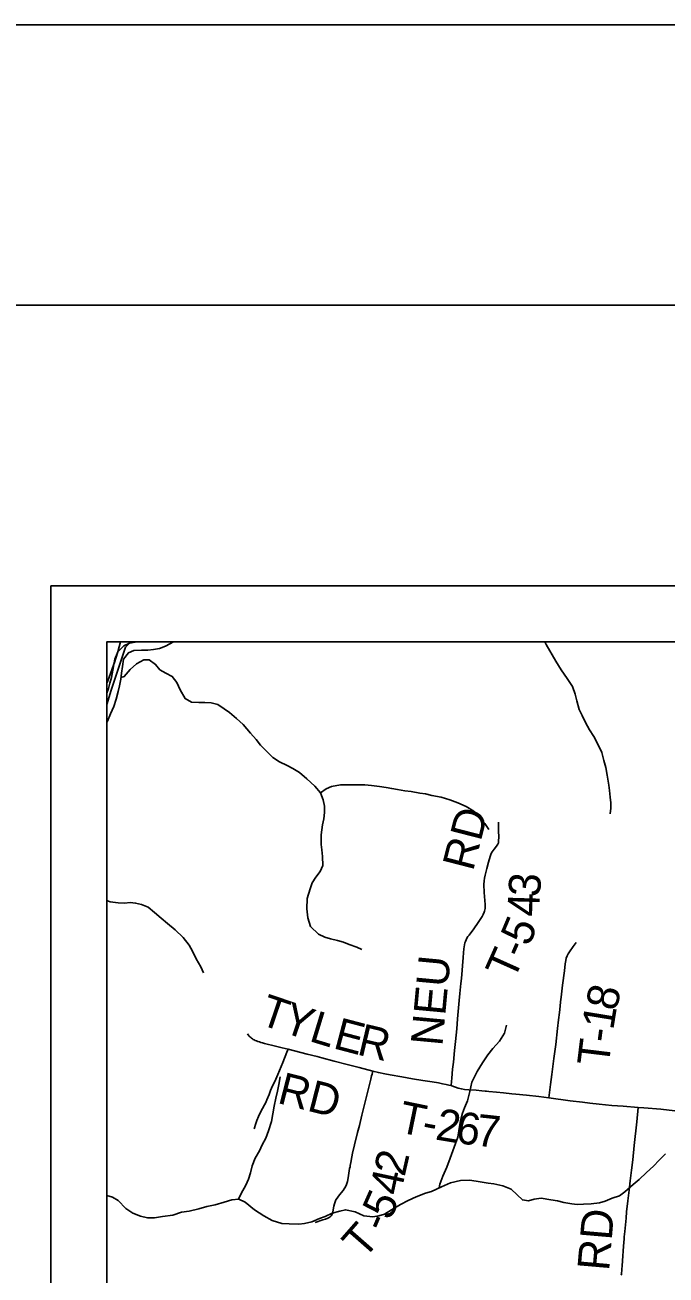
# Model space of a CAD drawing. Extents: x 0 to 34, y 0 to 22.
# Drawn here: x 2.168 to 3.312, y 19.77 to 22 of the extents above; entities that cross this region are included whole.
import ezdxf

# ---------------------------------------------------------------- set-up
doc = ezdxf.new("R2010")
doc.units = 0
for name, color, linetype in [('Default', 7, 'Continuous'), ('GM_X_County_Road', 7, 'Continuous'), ('GM_X_Minor_River', 7, 'Continuous'), ('GM_X_Township_Road', 7, 'Continuous'), ('GM_X_Township_Road_Text', 7, 'Continuous'), ('SH_Border', 7, 'Continuous'), ('SH_Cut_Line', 7, 'Continuous'), ('SH_Data', 7, 'Continuous')]:
    doc.layers.add(name, color=color, linetype=linetype)

msp = doc.modelspace()

# ---------------------------------------------------------------- linework, layer by layer
at = {"layer": 'Default'}
msp.add_lwpolyline([(8.6167, 20.8996), (2.3571, 20.8996), (2.3471, 20.8898), (2.3219, 20.8131), (2.3142, 20.7876), (2.3142, 19.0219)], dxfattribs=at)
msp.add_lwpolyline([(2.3571, 20.8996), (2.3142, 20.8996), (2.3142, 20.7876), (2.3219, 20.8131), (2.3471, 20.8898)], close=True, dxfattribs=at)
at = {"layer": 'GM_X_County_Road'}
msp.add_lwpolyline([(2.3142, 20.8255), (2.3158, 20.8301), (2.3282, 20.8645), (2.3302, 20.8704), (2.3335, 20.8817), (2.3383, 20.8996)], dxfattribs=at)
at = {"layer": 'GM_X_Minor_River'}
for points in [[(2.3142, 20.7553), (2.3152, 20.7582), (2.3207, 20.771), (2.3262, 20.7842), (2.3306, 20.797), (2.3342, 20.8106), (2.3363, 20.8208), (2.3387, 20.8329), (2.34, 20.8435), (2.3417, 20.8553), (2.3439, 20.8685), (2.3524, 20.8797), (2.3623, 20.8841), (2.3759, 20.8847), (2.3869, 20.8845), (2.3971, 20.8859), (2.4081, 20.8876), (2.4188, 20.8916), (2.4329, 20.8994), (2.4335, 20.8996)], [(2.3794, 20.8996), (2.3784, 20.8994), (2.3682, 20.8992), (2.3542, 20.8972), (2.3443, 20.8924), (2.3339, 20.8815), (2.328, 20.8687), (2.3267, 20.8589), (2.3246, 20.8491), (2.3221, 20.8358), (2.3193, 20.826), (2.3169, 20.8162), (2.3142, 20.8078)], [(3.096, 20.8996), (3.0979, 20.8948), (3.1155, 20.8649), (3.1251, 20.8496), (3.1358, 20.8339), (3.1451, 20.8201), (3.1498, 20.806), (3.1526, 20.7945), (3.1569, 20.7789), (3.1624, 20.7682), (3.1682, 20.7556), (3.1752, 20.7426), (3.1833, 20.7304), (3.1914, 20.7143), (3.1972, 20.7021), (3.2012, 20.6876), (3.2048, 20.6754), (3.2068, 20.6617), (3.2099, 20.6438), (3.2113, 20.6343), (3.2126, 20.6226), (3.2136, 20.6123), (3.2134, 20.6025), (3.2125, 20.5926)], [(2.3391, 20.836), (2.3452, 20.8378), (2.3557, 20.8501), (2.3672, 20.8605), (2.3798, 20.8672), (2.3896, 20.8674), (2.4009, 20.8593), (2.4086, 20.8493), (2.4191, 20.8434), (2.4308, 20.8376), (2.4389, 20.8268), (2.4448, 20.8138), (2.4536, 20.7982), (2.4648, 20.7919), (2.4781, 20.791), (2.4887, 20.7915), (2.5, 20.7906), (2.5121, 20.7878), (2.5233, 20.78), (2.533, 20.7734), (2.5454, 20.763), (2.5573, 20.7522), (2.5707, 20.7364), (2.5803, 20.7253), (2.5885, 20.7153), (2.5981, 20.7053), (2.6104, 20.693), (2.622, 20.6852), (2.6359, 20.6789), (2.6457, 20.6738), (2.6581, 20.6664), (2.6711, 20.6552), (2.6853, 20.6421), (2.6953, 20.6298), (2.7004, 20.6176), (2.7025, 20.6066), (2.7023, 20.5952), (2.701, 20.5835), (2.6989, 20.5729), (2.6963, 20.5551), (2.6968, 20.538), (2.6978, 20.5285), (2.6991, 20.5167), (2.6996, 20.5004), (2.6945, 20.4895), (2.6868, 20.4794), (2.6805, 20.4696), (2.677, 20.459), (2.6718, 20.4417), (2.6711, 20.4231), (2.6727, 20.4071), (2.6777, 20.3915), (2.6915, 20.378), (2.7032, 20.3725), (2.7133, 20.3697), (2.7258, 20.3669), (2.7363, 20.3637), (2.7465, 20.3597), (2.7604, 20.355), (2.7694, 20.3506)], [(2.6953, 20.6298), (2.7053, 20.6372), (2.7152, 20.6413), (2.7311, 20.6441), (2.7436, 20.6446), (2.7743, 20.6441), (2.7864, 20.6432), (2.8007, 20.6411), (2.8128, 20.6394), (2.8226, 20.6377), (2.8328, 20.636), (2.846, 20.6336), (2.8573, 20.6322), (2.8724, 20.6297), (2.8826, 20.6281), (2.8939, 20.6256), (2.9105, 20.6223), (2.926, 20.6179), (2.9407, 20.6124), (2.9553, 20.6057), (2.9688, 20.5971), (2.9781, 20.5868), (2.9885, 20.5752), (2.9959, 20.5649)], [(2.3142, 20.4378), (2.3197, 20.4357), (2.334, 20.4336), (2.3454, 20.4334), (2.3556, 20.4344), (2.3654, 20.4335), (2.376, 20.4311), (2.388, 20.426), (2.3992, 20.4167), (2.4108, 20.4063), (2.4224, 20.397), (2.4358, 20.3854), (2.4503, 20.3719), (2.4607, 20.3585), (2.4666, 20.3474), (2.4732, 20.334), (2.482, 20.3194), (2.4868, 20.3091)], [(2.907, 19.9255), (2.9082, 19.932), (2.9138, 19.946), (2.9209, 19.9625), (2.9268, 19.9784), (2.9315, 19.9912), (2.9363, 20.0044), (2.9403, 20.0157), (2.9436, 20.0346), (2.9453, 20.0449), (2.9486, 20.0585), (2.9521, 20.0683), (2.9576, 20.0807), (2.9617, 20.0973), (2.9654, 20.1136), (2.9748, 20.1328), (2.9845, 20.1486), (2.9942, 20.1628), (3.0027, 20.1737), (3.0146, 20.1868), (3.0236, 20.2011), (3.0276, 20.2158)], [(2.5491, 19.9052), (2.5537, 19.9155), (2.5619, 19.9302), (2.567, 19.9411), (2.5706, 19.952), (2.5734, 19.9645), (2.579, 19.9785), (2.5864, 19.9916), (2.5915, 20.0022), (2.5977, 20.0142), (2.6028, 20.027), (2.6077, 20.0436), (2.6105, 20.0576), (2.6127, 20.0709), (2.6159, 20.0856), (2.6188, 20.0977), (2.6212, 20.1098), (2.6234, 20.1234)], [(2.3142, 19.9117), (2.3242, 19.9088), (2.3343, 19.9026), (2.3481, 19.8887), (2.3605, 19.8802), (2.374, 19.8747), (2.3868, 19.8718), (2.3989, 19.872), (2.4134, 19.874), (2.4316, 19.8768), (2.4472, 19.8819), (2.4608, 19.8839), (2.4779, 19.8878), (2.4927, 19.8918), (2.5076, 19.8953), (2.5232, 19.8997), (2.5369, 19.904), (2.5497, 19.9053), (2.561, 19.8998), (2.5778, 19.8863), (2.5943, 19.8754), (2.6089, 19.8672), (2.6262, 19.862), (2.6395, 19.8611), (2.6569, 19.8608), (2.6667, 19.8618), (2.6797, 19.865), (2.6938, 19.8705), (2.7037, 19.8741), (2.7162, 19.88), (2.7296, 19.8839), (2.7402, 19.8864), (2.7575, 19.8828), (2.7726, 19.8757), (2.7888, 19.8739), (2.7994, 19.8757), (2.8093, 19.8785), (2.8219, 19.8863), (2.8384, 19.8955), (2.8521, 19.9025), (2.8662, 19.9091), (2.8826, 19.9157), (2.8933, 19.919), (2.9112, 19.9274), (2.9276, 19.9344), (2.9451, 19.9383), (2.9617, 19.9388), (2.9802, 19.9358), (2.9949, 19.9337), (3.0048, 19.9324), (3.0206, 19.9288), (3.0356, 19.9228), (3.0461, 19.9128), (3.0558, 19.9039), (3.0667, 19.9019), (3.0766, 19.9051), (3.0895, 19.9068), (3.1065, 19.9039), (3.1182, 19.9022), (3.1295, 19.8994), (3.1438, 19.8969), (3.1537, 19.8956), (3.1646, 19.8962), (3.1783, 19.8967), (3.1935, 19.8988), (3.2033, 19.9016), (3.2159, 19.9068), (3.2289, 19.9111), (3.2388, 19.9185), (3.2534, 19.9316), (3.2642, 19.9402), (3.2772, 19.9529), (3.2895, 19.964), (3.2996, 19.9749), (3.3111, 19.9861)]]:
    msp.add_lwpolyline(points, dxfattribs=at)
at = {"layer": 'GM_X_Township_Road'}
for points in [[(2.9284, 20.1078), (2.929, 20.115), (2.9296, 20.1212), (2.9311, 20.1371), (2.9325, 20.1498), (2.9346, 20.1705), (2.9363, 20.1866), (2.9385, 20.2092), (2.94, 20.2268), (2.9427, 20.2593), (2.944, 20.2723), (2.9461, 20.2902), (2.9468, 20.2988), (2.9501, 20.3365), (2.9506, 20.3444), (2.9512, 20.3518), (2.9516, 20.3552), (2.9523, 20.3591), (2.9532, 20.3626), (2.954, 20.365), (2.9551, 20.3678), (2.9565, 20.3706), (2.9586, 20.3737), (2.9604, 20.3762), (2.9689, 20.3877), (2.9769, 20.3988), (2.9841, 20.4097), (2.9858, 20.4129), (2.9875, 20.417), (2.9881, 20.4187), (2.9887, 20.4212), (2.9891, 20.4236), (2.9894, 20.4267), (2.9892, 20.431), (2.9874, 20.4522), (2.987, 20.4668), (2.9874, 20.4731), (2.9881, 20.4778), (2.9891, 20.4833), (2.9921, 20.4952), (2.995, 20.5064), (2.9979, 20.5163), (3, 20.5216), (3.0017, 20.5249), (3.0035, 20.5274), (3.0051, 20.5295), (3.0097, 20.5351), (3.0118, 20.5384), (3.0128, 20.5407), (3.0133, 20.5431), (3.0135, 20.5521), (3.0133, 20.5612), (3.0131, 20.578)], [(3.1031, 20.0859), (3.1061, 20.1095), (3.1084, 20.1276), (3.1121, 20.1561), (3.1153, 20.1811), (3.1186, 20.2095), (3.1202, 20.2249), (3.1219, 20.2384), (3.1231, 20.2495), (3.124, 20.2575), (3.125, 20.2655), (3.1275, 20.287), (3.1306, 20.3123), (3.132, 20.3252), (3.133, 20.3307), (3.1341, 20.3349), (3.1356, 20.339), (3.1375, 20.3429), (3.1398, 20.3466), (3.1463, 20.356), (3.1519, 20.3632)], [(2.5648, 20.2003), (2.5661, 20.1982), (2.5681, 20.1959), (2.5695, 20.1945), (2.5708, 20.1934), (2.5723, 20.1922), (2.5738, 20.1911), (2.5754, 20.1901), (2.577, 20.1893), (2.5789, 20.1884), (2.581, 20.1875), (2.5835, 20.1866), (2.5862, 20.1857), (2.5888, 20.1848), (2.5919, 20.1841), (2.5956, 20.1831), (2.6151, 20.1783), (2.6269, 20.1754), (2.6376, 20.1728)], [(2.5772, 20.0306), (2.5801, 20.0404), (2.5817, 20.0457), (2.5844, 20.0525), (2.5875, 20.0592), (2.5916, 20.0667), (2.5956, 20.0737), (2.5975, 20.0776), (2.5996, 20.0821), (2.6035, 20.0919), (2.6063, 20.0988), (2.6099, 20.1074), (2.6136, 20.1153), (2.6191, 20.1278), (2.6279, 20.149), (2.6354, 20.1673), (2.6376, 20.1728)], [(2.6376, 20.1728), (2.6713, 20.164), (2.6893, 20.1595), (2.6977, 20.1573), (2.7197, 20.1516), (2.7432, 20.1454), (2.7644, 20.1399), (2.7885, 20.1335)], [(2.6856, 19.8638), (2.6997, 19.8683), (2.7042, 19.8695), (2.7083, 19.871), (2.7111, 19.8724), (2.7126, 19.8735), (2.7143, 19.8752), (2.7158, 19.8772), (2.7168, 19.8795), (2.7175, 19.8818), (2.718, 19.8861), (2.7191, 19.8928), (2.7201, 19.897), (2.7214, 19.9005), (2.7229, 19.9038), (2.7249, 19.9069), (2.7274, 19.9103), (2.7325, 19.9167), (2.7356, 19.9205), (2.7378, 19.9238), (2.74, 19.9273), (2.7418, 19.9314), (2.7434, 19.9368), (2.7446, 19.9435), (2.7466, 19.9557), (2.7474, 19.9599), (2.748, 19.963), (2.7484, 19.9654), (2.7493, 19.9703), (2.7512, 19.9806), (2.7526, 19.9873), (2.756, 20.0018), (2.7616, 20.0241), (2.7648, 20.0367), (2.7691, 20.0548), (2.7762, 20.0838), (2.7796, 20.0976), (2.785, 20.1192), (2.7866, 20.1252), (2.7873, 20.1282), (2.7885, 20.1335)], [(2.7885, 20.1335), (2.7988, 20.131), (2.8104, 20.1285), (2.8198, 20.1268), (2.8405, 20.1234), (2.8593, 20.1201), (2.8777, 20.1171), (2.8946, 20.1144), (2.9058, 20.1125), (2.913, 20.1111), (2.9198, 20.1096), (2.9244, 20.1087), (2.9284, 20.1078)], [(2.9284, 20.1078), (2.9326, 20.1062), (2.9362, 20.1048), (2.9408, 20.1033), (2.9441, 20.1023), (2.9468, 20.1018), (2.9521, 20.101), (2.9601, 20.1002), (2.9732, 20.0994), (2.9831, 20.0987), (2.9892, 20.0981), (2.9917, 20.0979), (2.996, 20.0975), (3.0095, 20.096), (3.0218, 20.0947), (3.0366, 20.0933), (3.044, 20.0925), (3.0632, 20.0905), (3.0848, 20.0884), (3.1031, 20.0859)], [(3.1031, 20.0859), (3.141, 20.0808), (3.1628, 20.078), (3.1763, 20.0766), (3.1926, 20.0748), (3.2153, 20.0725), (3.2354, 20.0709), (3.2625, 20.0687)], [(3.232, 19.7695), (3.2323, 19.7713), (3.2326, 19.7737), (3.2331, 19.7773), (3.2334, 19.7804), (3.2338, 19.7865), (3.2344, 19.7952), (3.2362, 19.8212), (3.2373, 19.8342), (3.2376, 19.8377), (3.2385, 19.8472), (3.2408, 19.8712), (3.2418, 19.8823), (3.2441, 19.902), (3.2463, 19.9212), (3.2483, 19.9378), (3.2506, 19.9569), (3.2527, 19.9754), (3.2551, 20.0007), (3.2598, 20.0432), (3.2625, 20.0687)], [(3.2625, 20.0687), (3.2725, 20.0682), (3.3026, 20.0655), (3.3581, 20.059)]]:
    msp.add_lwpolyline(points, dxfattribs=at)
at = {"layer": 'SH_Border'}
msp.add_lwpolyline([(1.5, 21.5), (33.5, 21.5), (33.5, 0.5), (1.5, 0.5)], close=True, dxfattribs=at)
at = {"layer": 'SH_Cut_Line'}
msp.add_lwpolyline([(0, 0), (34, 0), (34, 22), (0, 22)], close=True, dxfattribs=at)
msp.add_lwpolyline([(9.1142, 20.8996), (2.3142, 20.8996), (2.3142, 19.0219)], dxfattribs=at)
at = {"layer": 'SH_Data'}
for p, q in [((2.2142, 20.9996), (9.2142, 20.9996)), ((2.2142, 20.9996), (2.2142, 13.9996)), ((2.3142, 20.8996), (2.3142, 14.0996)), ((2.3142, 20.8996), (9.1142, 20.8996))]:
    msp.add_line(p, q, dxfattribs=at)

# ---------------------------------------------------------------- texts
at = {"layer": 'GM_X_Township_Road_Text'}
for s, height, rotation, p in [('RD', 0.05682, 75.6064, (2.9675, 20.4888)), ('3', 0.0568, 85.7967, (3.0867, 20.4431)), ('4', 0.0568, 88.3101, (3.0857, 20.4087)), ('5', 0.0568, 67.1646, (3.0673, 20.3543)), ('-', 0.0568, 66.0714, (3.0574, 20.3319)), ('T', 0.0568, 65.8582, (3.0399, 20.2929)), ('NEU', 0.05682, 84.6855, (2.9128, 20.1771)), ('8', 0.0568, 77.0682, (3.2232, 20.2391)), ('T', 0.0568, 341.1842, (2.5837, 20.2181)), ('Y', 0.0568, 341.3488, (2.6241, 20.2044)), ('L', 0.0568, 343.0379, (2.6732, 20.1878)), ('E', 0.0568, 345.2555, (2.7161, 20.1748)), ('1', 0.0568, 80.7515, (3.2177, 20.2055)), ('R', 0.0568, 346.6792, (2.7587, 20.1636)), ('-', 0.0568, 82.4456, (3.2147, 20.1828)), ('T', 0.0568, 83.0531, (3.2096, 20.1408)), ('RD', 0.05682, 345.6062, (2.6164, 20.0772)), ('T', 0.0568, 348.377, (2.8317, 20.0252)), ('2', 0.0568, 350.6451, (2.8987, 20.0118)), ('6', 0.0568, 352.2256, (2.9349, 20.0059)), ('7', 0.0568, 353.7613, (2.9712, 20.0009)), ('-', 0.0568, 349.0511, (2.8741, 20.0165)), ('2', 0.0568, 77.1345, (2.8453, 19.9438)), ('4', 0.0568, 77.9086, (2.8381, 19.9097)), ('5', 0.0568, 65.9295, (2.8198, 19.8655)), ('-', 0.0568, 66.79, (2.8107, 19.8442)), ('RD', 0.05682, 85.0738, (3.2103, 19.7761)), ('T', 0.0568, 48.7877, (2.7723, 19.7959))]:
    msp.add_text(s, height=height, rotation=rotation, dxfattribs=at).set_placement(p)

doc.saveas('drawing.dxf')
